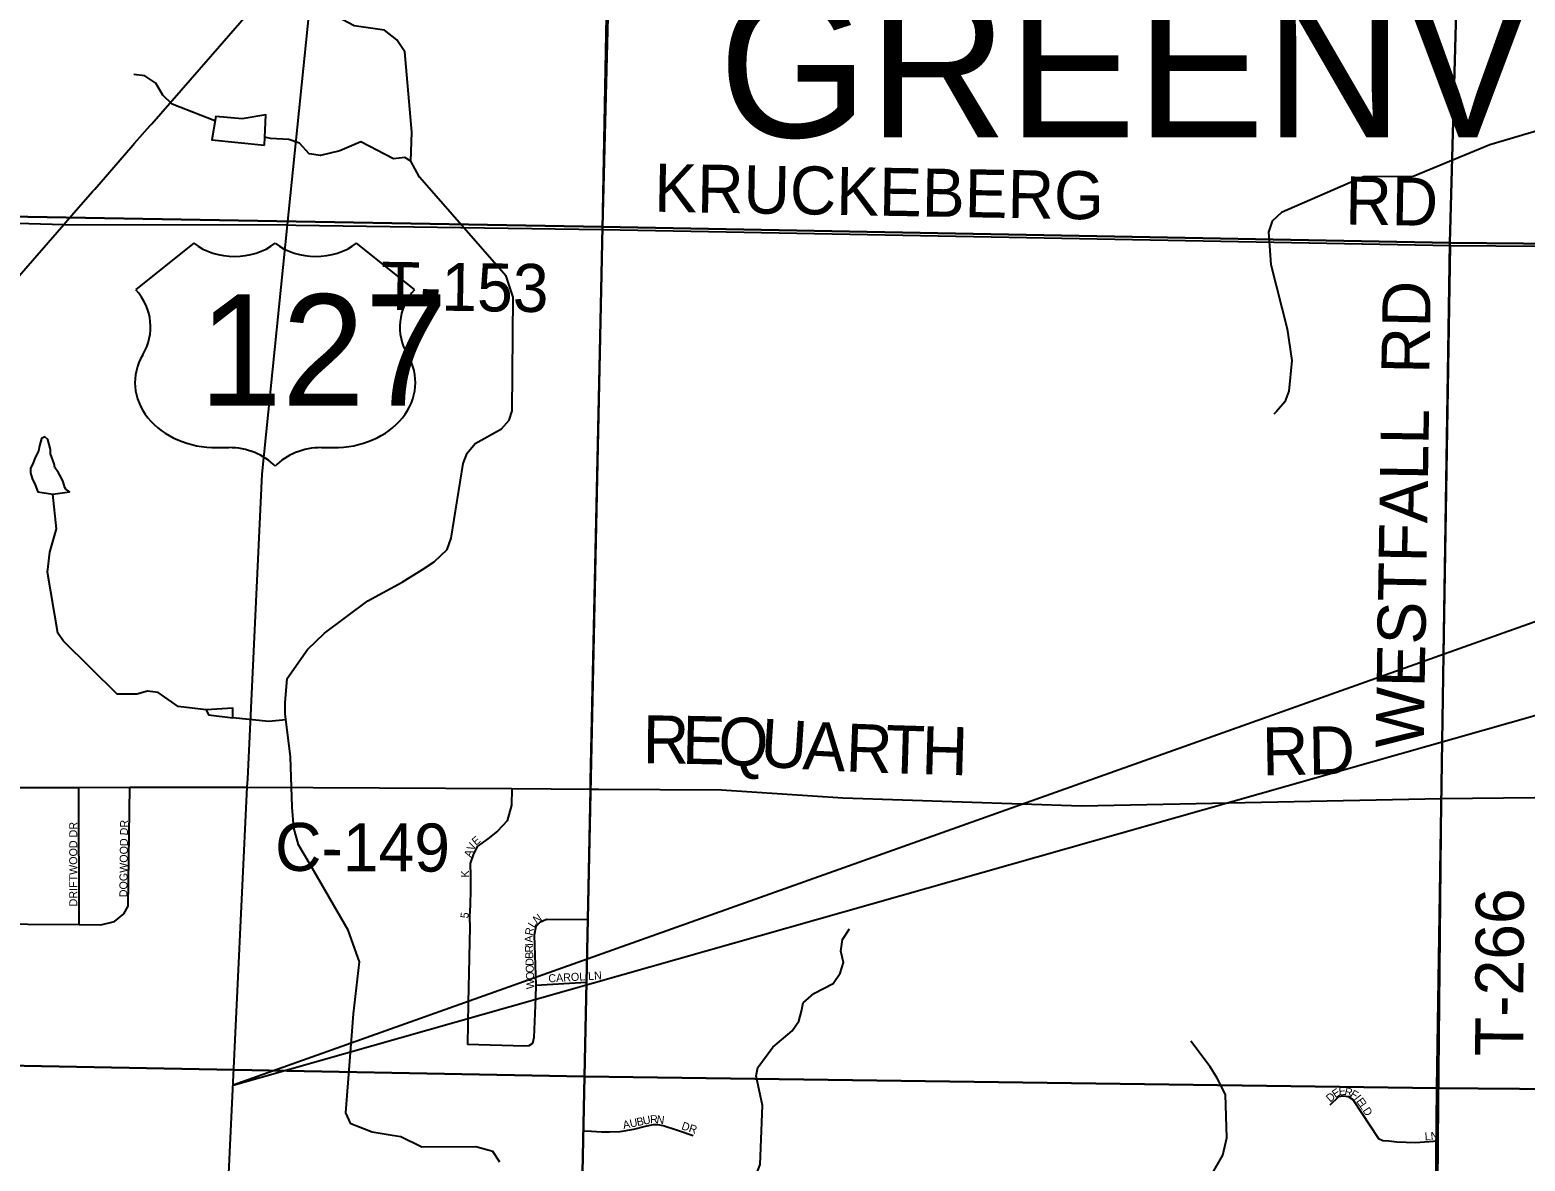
# Model space of a CAD drawing. Extents: x -784 to 1375, y -225 to 440.
# Drawn here: x 321.44 to 357.92, y 361.88 to 389.47 of the extents above; entities that cross this region are included whole.
import ezdxf

# ---------------------------------------------------------------- set-up
doc = ezdxf.new("R2010")
doc.units = 0
for name, color, linetype in [('GM_X_City_Street', 7, 'Continuous'), ('GM_X_City_Street_Text', 7, 'Continuous'), ('GM_X_County_Road', 7, 'Continuous'), ('GM_X_County_Road_Text', 7, 'Continuous'), ('GM_X_Minor_Lake', 7, 'Continuous'), ('GM_X_Minor_River', 7, 'Continuous'), ('GM_X_Section', 7, 'Continuous'), ('GM_X_State_Route', 7, 'Continuous'), ('GM_X_Township_Road', 7, 'Continuous'), ('GM_X_Township_Road_Text', 7, 'Continuous'), ('GM_X_Township_Subdivision', 7, 'Continuous'), ('GM_X_Township_Subdivision_Text', 7, 'Continuous'), ('GM_X_Township_Text', 7, 'Continuous'), ('GM_X_US_Location', 7, 'Continuous'), ('GM_X_US_Route', 7, 'Continuous'), ('GM_X_US_Shield', 7, 'Continuous'), ('SH_Text', 7, 'Continuous')]:
    doc.layers.add(name, color=color, linetype=linetype)

msp = doc.modelspace()

# ---------------------------------------------------------------- linework, layer by layer
at = {"layer": 'GM_X_City_Street'}
for points in [[(320.207, 367.666), (321.394, 367.658), (322.642, 367.65), (323.176, 367.646), (323.509, 367.729), (323.735, 367.91), (323.843, 368.102), (323.878, 370.999)], [(320.337, 370.994), (321.428, 370.996), (322.198, 370.997)], [(322.198, 370.997), (322.198, 370.997), (322.637, 370.997), (323.878, 370.999), (324.886, 371.001), (324.886, 371.001)], [(322.642, 367.65), (322.637, 370.997)]]:
    msp.add_lwpolyline(points, dxfattribs=at)
at = {"layer": 'GM_X_County_Road'}
for points in [[(335.324, 370.954), (338.32, 370.935), (341.28, 370.742), (347.104, 370.545), (355.882, 370.725), (360.422, 370.773), (364.01, 370.778), (365.588, 370.951), (371.777, 372.241), (373.481, 372.653), (374.961, 373.068)], [(324.886, 371.001), (326.746, 371.004)], [(326.746, 371.004), (333.198, 370.967), (335.118, 370.955)], [(335.118, 370.955), (335.324, 370.954)]]:
    msp.add_lwpolyline(points, dxfattribs=at)
at = {"layer": 'GM_X_Minor_Lake'}
for points in [[(326.619, 387.3), (325.977, 387.359), (325.88, 386.794), (327.164, 386.659)], [(327.164, 386.659), (327.202, 387.398), (326.619, 387.3)], [(322.319, 378.269), (322.297, 378.313), (322.253, 378.446), (322.208, 378.556), (322.142, 378.666), (322.054, 378.799), (322.031, 378.887), (321.943, 379.13), (321.943, 379.241), (321.877, 379.483), (321.81, 379.549), (321.722, 379.505), (321.7, 379.417), (321.678, 379.329), (321.656, 379.196), (321.568, 379.042), (321.523, 378.909), (321.457, 378.777), (321.457, 378.666), (321.501, 378.534), (321.568, 378.379), (321.634, 378.203), (322.001, 378.149)], [(322.001, 378.149), (322.407, 378.203), (322.319, 378.269)], [(326.394, 372.691), (326.39, 372.926), (325.746, 372.891)], [(325.746, 372.891), (325.798, 372.765), (326.394, 372.691)]]:
    msp.add_lwpolyline(points, dxfattribs=at)
at = {"layer": 'GM_X_Minor_River'}
for points in [[(330.737, 386.272), (330.758, 386.976), (330.59, 388.938), (330.392, 389.231), (330.098, 389.464), (329.354, 389.571), (328.805, 389.862)], [(360.385, 389.128), (360.19, 388.85), (359.735, 388.475), (359.328, 387.253), (359.082, 387.148), (358.358, 387.052), (357.063, 386.669), (355.473, 386.01), (355.196, 385.898), (353.979, 385.889), (351.984, 385.018), (351.752, 384.803), (351.661, 384.538), (351.717, 383.746), (352.12, 382.18), (352.231, 381.41), (352.162, 380.66), (352.063, 380.403), (351.855, 380.164), (351.791, 380.103)], [(325.958, 387.253), (324.915, 387.658), (324.687, 387.878), (324.516, 388.175), (324.248, 388.349), (323.982, 388.382)], [(330.737, 386.272), (330.59, 386.361), (330.314, 386.327), (329.513, 386.741), (329.007, 386.523), (328.533, 386.406), (328.259, 386.451), (328.021, 386.713), (327.763, 386.796), (327.316, 386.82), (327.174, 386.855)], [(331.021, 376.312), (331.309, 376.494), (331.621, 376.801), (331.72, 377.074), (332.013, 378.894), (332.112, 379.15), (332.305, 379.382), (332.948, 379.738), (333.14, 379.954), (333.207, 380.18), (333.235, 382.952), (333.064, 383.464), (330.95, 385.876), (330.737, 386.272)], [(325.746, 372.891), (325.056, 372.966), (324.568, 373.312), (324.309, 373.34), (324.049, 373.267), (323.57, 373.268), (322.259, 374.561), (322.121, 374.759), (321.874, 376.244), (321.931, 376.736), (322.09, 377.305), (322.001, 378.149)], [(332.907, 361.853), (332.736, 362.118), (332.324, 362.234), (331.004, 362.226), (330.494, 362.471), (330.283, 362.51), (329.791, 362.59), (329.272, 362.789), (329.148, 363.06), (329.334, 365.472), (329.481, 366.746), (329.21, 367.517), (328.284, 369.12), (327.994, 369.593), (327.883, 370.013), (327.838, 370.517), (327.797, 371.741), (327.667, 372.793), (327.672, 373.059), (327.723, 373.654), (328.216, 374.359), (328.631, 374.76), (329.687, 375.548), (330.528, 376.005), (331.021, 376.312)], [(327.686, 372.643), (327.271, 372.604), (326.394, 372.691)], [(337.81, 358.525), (338.062, 358.666), (338.316, 358.955), (338.512, 359.419), (338.551, 359.858), (338.481, 360.536), (338.608, 360.806), (339.048, 361.254), (339.263, 361.796), (339.314, 363.239), (339.166, 363.958), (339.205, 364.169), (339.568, 364.659), (340.038, 365.058), (340.203, 365.296), (340.266, 365.537), (340.313, 365.739), (340.572, 365.966), (341.044, 366.216), (341.21, 366.469), (341.29, 366.726), (341.229, 367.003), (341.27, 367.284), (341.436, 367.545)], [(354.952, 354.917), (354.007, 355.345), (353.239, 355.6), (353.049, 355.804), (352.889, 356.375), (352.898, 357.301), (352.823, 358.089), (352.526, 359.026), (351.767, 360.231), (351.548, 360.482), (351.092, 360.687), (350.516, 360.825), (350.239, 361), (350.201, 361.268), (350.265, 361.533), (350.55, 362.025), (350.643, 362.446), (350.61, 363.507), (350.411, 363.907), (350.24, 364.18), (349.77, 364.804)]]:
    msp.add_lwpolyline(points, dxfattribs=at)
at = {"layer": 'GM_X_Section'}
for points in [[(315.331, 405.821), (335.943, 405.436), (335.412, 384.667), (314.846, 385.028)], [(356.656, 405.065), (356.086, 384.279), (335.412, 384.667), (335.943, 405.436)], [(314.846, 385.028), (335.412, 384.667), (334.976, 363.947), (314.451, 364.338)], [(335.412, 384.667), (356.086, 384.279), (355.77, 363.658), (334.976, 363.947)], [(314.451, 364.338), (334.976, 363.947), (334.534, 342.899), (313.882, 343.598)], [(334.976, 363.947), (355.77, 363.658), (355.556, 342.355), (350.439, 342.394), (334.534, 342.899)]]:
    msp.add_lwpolyline(points, close=True, dxfattribs=at)
for points in [[(374.961, 384.105), (356.086, 384.279), (356.656, 405.065), (374.961, 405.1)], [(374.961, 363.509), (355.77, 363.658), (356.086, 384.279), (374.961, 384.105)], [(374.961, 342.202), (370.946, 342.229), (355.556, 342.355), (355.77, 363.658), (374.961, 363.509)]]:
    msp.add_lwpolyline(points, dxfattribs=at)
at = {"layer": 'GM_X_State_Route'}
for points in [[(324.376, 387.14), (324.415, 387.184), (326.781, 389.893), (328.344, 391.607), (328.619, 391.897)], [(323.955, 386.658), (323.997, 386.706), (324.376, 387.14)], [(322.973, 385.532), (323.023, 385.59), (323.955, 386.658)], [(322.411, 384.889), (322.466, 384.953), (322.973, 385.532)], [(319.641, 381.718), (322.271, 384.729), (322.411, 384.889)]]:
    msp.add_lwpolyline(points, dxfattribs=at)
at = {"layer": 'GM_X_Township_Road'}
for points in [[(335.123, 371.162), (335.417, 384.601), (335.692, 399.367)], [(320.278, 384.782), (322.271, 384.729)], [(322.271, 384.729), (327.729, 384.715), (327.931, 384.712)], [(327.931, 384.712), (335.417, 384.601)], [(335.417, 384.601), (356.105, 384.217), (374.961, 384.078)], [(355.783, 360.117), (355.804, 362.373), (355.882, 370.725), (356.105, 384.217)], [(335.118, 370.955), (335.123, 371.162)], [(334.681, 347.84), (334.731, 351.148), (334.814, 354.657), (334.82, 356.384), (334.852, 357.958), (334.948, 362.619), (335.022, 366.247), (335.053, 367.767), (335.118, 370.955)]]:
    msp.add_lwpolyline(points, dxfattribs=at)
at = {"layer": 'GM_X_Township_Subdivision'}
for points in [[(333.198, 370.967), (333.189, 370.566), (333.09, 370.178), (332.854, 369.926), (332.617, 369.742), (332.355, 369.558), (332.254, 369.352), (332.185, 369.14), (332.19, 368.84), (332.19, 368.501), (332.185, 368.127), (332.171, 367.847), (332.18, 367.566), (332.171, 367.245), (332.161, 366.829), (332.141, 366.116), (332.136, 365.732), (332.126, 365.23), (332.116, 364.724)], [(335.053, 367.767), (334.051, 367.772), (333.887, 367.704), (333.789, 367.601), (333.744, 367.389), (333.79, 366.176), (333.779, 365.875), (333.735, 364.896), (333.705, 364.748), (333.612, 364.694), (333.508, 364.684), (332.116, 364.724)], [(333.79, 366.176), (335.022, 366.247)], [(353.164, 363.253), (353.379, 363.455), (353.485, 363.478), (353.61, 363.455), (353.719, 363.385), (354.345, 362.436), (354.451, 362.383), (354.596, 362.373), (354.791, 362.353), (355.248, 362.336), (355.804, 362.373)], [(335.143, 362.61), (335.389, 362.598), (335.585, 362.595), (335.843, 362.605), (336.179, 362.663), (336.464, 362.734), (336.657, 362.775), (336.759, 362.778), (336.891, 362.754), (337.243, 362.639), (337.627, 362.507)], [(334.948, 362.619), (335.143, 362.61)]]:
    msp.add_lwpolyline(points, dxfattribs=at)
at = {"layer": 'GM_X_US_Route'}
for points in [[(326.756, 371.206), (326.756, 371.209), (327.109, 378.633), (327.729, 384.715), (328.257, 389.882), (328.263, 390.004), (328.268, 390.092), (328.273, 390.205), (328.344, 391.607)], [(326.136, 358.154), (326.746, 371.004), (326.756, 371.206)]]:
    msp.add_lwpolyline(points, dxfattribs=at)
at = {"layer": 'GM_X_US_Shield'}
for p, q in [((325.444, 384.269), (324.028, 383.136)), ((330.826, 383.136), (329.41, 384.269)), ((326.011, 379.284), (326.294, 379.284)), ((328.56, 379.284), (328.843, 379.284))]:
    msp.add_line(p, q, dxfattribs=at)
for centre, major_axis, start_param, end_param in [((326.436, 385.078), (-1.416, 0), 0.795399, 2.346194), ((328.418, 385.078), (-1.416, 0), 0.795399, 2.346194), ((322.404, 382.226), (1.983, 0), 5.838949, 6.894067), ((332.45, 382.226), (-1.983, 0), 5.672304, 6.727422), ((325.989, 380.87), (1.983, 0), 2.702327, 4.723529), ((328.865, 380.87), (-1.983, 0), 1.559657, 3.580859), ((326.294, 378.151), (-1.416, 0), 3.785094, 4.712389), ((328.56, 378.151), (-1.416, 0), 4.712389, 5.639684)]:
    msp.add_ellipse(centre, major_axis=major_axis, ratio=0.8, start_param=start_param, end_param=end_param, dxfattribs=at)
at = {"layer": 'SH_Text'}
msp.add_lwpolyline([(380.581, 383.008), (326.401, 363.733), (380.581, 379.115)], close=True, dxfattribs=at)

# ---------------------------------------------------------------- texts
at = {"layer": 'GM_X_City_Street_Text'}
for s, height, rotation, p in [('DRIFTWOOD DR', 0.19531, 90, (322.598, 368.094)), ('DOGWOOD DR', 0.1953, 89.4035, (323.819, 368.317))]:
    msp.add_text(s, height=height, rotation=rotation, dxfattribs=at).set_placement(p)
at = {"layer": 'GM_X_County_Road_Text'}
for s, height, rotation, p in [('R', 1.172, 359.4536, (336.391, 371.583)), ('E', 1.172, 358.7442, (337.349, 371.574)), ('Q', 1.172, 357.3835, (338.218, 371.555)), ('U', 1.172, 356.3657, (339.243, 371.508)), ('A', 1.172, 356.8794, (340.283, 371.442)), ('R', 1.172, 357.8251, (341.334, 371.385)), ('T', 1.172, 358.3166, (342.307, 371.348)), ('H', 1.172, 358.3551, (343.184, 371.322)), ('RD', 1.1719, 0.9891, (351.516, 371.287)), ('C-149', 1.1719, 359.7247, (327.421, 368.962))]:
    msp.add_text(s, height=height, rotation=rotation, dxfattribs=at).set_placement(p)
at = {"layer": 'GM_X_Township_Road_Text'}
for s, rotation, p in [('KRUCKEBERG', 358.9862, (336.668, 385.038)), ('RD', 359.0128, (353.529, 384.728)), ('T-153', 359.1569, (329.996, 382.646)), ('RD', 89.0118, (355.587, 381.078)), ('WESTFALL', 89.0781, (355.449, 371.951)), ('T-266', 89.7193, (357.875, 364.44))]:
    msp.add_text(s, height=1.1719, rotation=rotation, dxfattribs=at).set_placement(p)
at = {"layer": 'GM_X_Township_Subdivision_Text'}
for s, height, rotation, p in [('V', 0.195, 64.0117, (332.265, 369.431)), ('E', 0.195, 40.9006, (332.328, 369.569)), ('A', 0.195, 69.9581, (332.208, 369.274)), ('K', 0.195, 90, (332.155, 368.798)), ('5', 0.195, 83.0362, (332.137, 367.795)), ('N', 0.195, 35.4424, (333.803, 367.661)), ('A', 0.195, 92.0056, (333.713, 367.215)), ('R', 0.195, 78.9984, (333.707, 367.375)), ('L', 0.195, 58.4493, (333.745, 367.559)), ('I', 0.195, 92.0002, (333.716, 367.129)), ('R', 0.195, 92.0038, (333.722, 366.974)), ('B', 0.195, 92.0099, (333.727, 366.82)), ('D', 0.195, 92.0002, (333.733, 366.648)), ('O', 0.195, 92.0056, (333.739, 366.476)), ('O', 0.195, 92.0056, (333.745, 366.304)), ('W', 0.195, 92.0052, (333.753, 366.081)), ('CAROL LN', 0.1953, 3.3191, (334.097, 366.24)), ('D', 0.195, 40.8384, (353.169, 363.307)), ('E', 0.195, 33.5461, (353.294, 363.415)), ('E', 0.195, 5.61, (353.385, 363.483)), ('R', 0.195, 345.843, (353.504, 363.498)), ('F', 0.195, 328.8113, (353.64, 363.466)), ('I', 0.195, 307.9018, (353.744, 363.407)), ('E', 0.195, 305.0994, (353.795, 363.341)), ('U', 0.195, 11.9624, (336.418, 362.767)), ('R', 0.195, 2.5022, (336.578, 362.802)), ('N', 0.195, 352.0183, (336.723, 362.809)), ('L', 0.195, 303.6939, (353.873, 363.23)), ('D', 0.195, 303.7027, (353.95, 363.115)), ('A', 0.195, 11.9539, (335.93, 362.664)), ('U', 0.195, 11.9582, (336.099, 362.7)), ('B', 0.195, 11.9374, (336.267, 362.735)), ('DR', 0.1953, 341.5632, (337.325, 362.663)), ('LN', 0.1953, 3.0113, (355.479, 362.389))]:
    msp.add_text(s, height=height, rotation=rotation, dxfattribs=at).set_placement(p)
at = {"layer": 'GM_X_Township_Text'}
msp.add_text('GREENVILLE', height=3.5156, rotation=0, dxfattribs=at).set_placement((338.243, 386.853))
at = {"layer": 'GM_X_US_Location'}
for s in ['0', '/']:
    msp.add_text(s, height=0.00391, dxfattribs=at).set_placement((327.429, 381.661))
msp.add_text('127', height=0.00391, rotation=0, dxfattribs=at).set_placement((326.227, 380.853))
at = {"layer": 'GM_X_US_Shield'}
msp.add_text('127', height=2.7191, dxfattribs=at).set_placement((325.569, 380.304))

doc.saveas('drawing.dxf')
